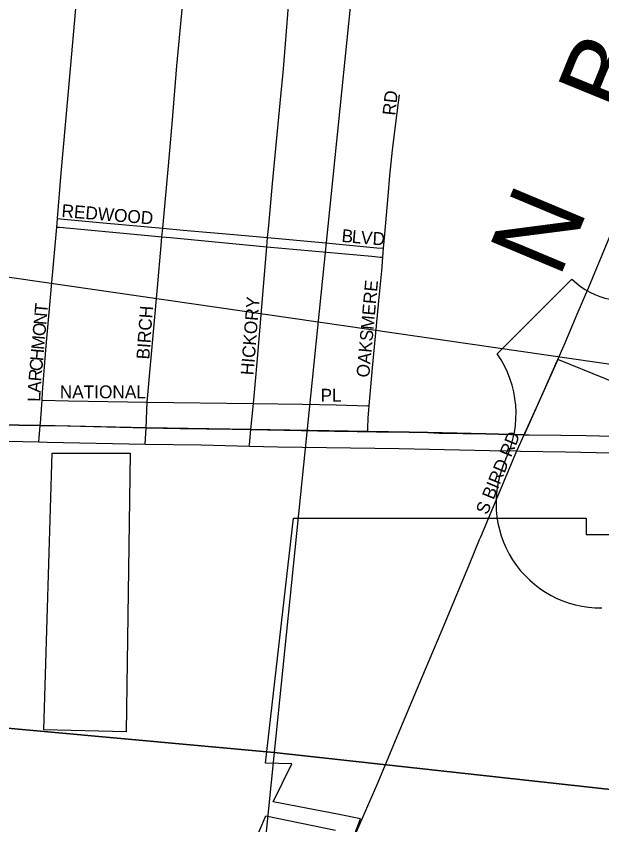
# Model space of a CAD drawing. Extents: x -209 to 4852, y 0 to 905.
# Drawn here: x 185.98 to 194.59, y 266.56 to 278.45 of the extents above; entities that cross this region are included whole.
import ezdxf

# ---------------------------------------------------------------- set-up
doc = ezdxf.new("R2010")
doc.units = 0
for name, color, linetype in [('GM_X_Airport_Location_Class_2', 7, 'Continuous'), ('GM_X_Airport_Location_Class_3', 7, 'Continuous'), ('GM_X_Corporation', 7, 'Continuous'), ('GM_X_County_ROW', 7, 'Continuous'), ('GM_X_Interchange_Ramps', 7, 'Continuous'), ('GM_X_Interstate_Location', 7, 'Continuous'), ('GM_X_Minor_River', 7, 'Continuous'), ('GM_X_Township_Road', 7, 'Continuous'), ('GM_X_Township_Text', 7, 'Continuous'), ('GM_X_US_Location', 7, 'Continuous'), ('SH_Text', 7, 'Continuous')]:
    doc.layers.add(name, color=color, linetype=linetype)

msp = doc.modelspace()

# ---------------------------------------------------------------- linework, layer by layer
at = {"layer": 'GM_X_Airport_Location_Class_2'}
msp.add_lwpolyline([(192.919, 271.064), (193.195, 271.724), (193.339, 272.058)], dxfattribs=at)
at = {"layer": 'GM_X_Corporation'}
for points in [[(185.391, 272.449), (186.331, 272.434), (186.734, 272.427), (187.887, 272.398), (188.395, 272.39), (189.152, 272.38), (189.428, 272.374), (190.657, 272.349), (190.989, 272.344), (191.146, 272.342), (191.275, 272.34), (191.445, 272.338), (191.752, 272.334), (192.029, 272.33), (192.201, 272.322), (192.88, 272.31), (193.444, 272.297), (193.52, 272.296), (193.983, 272.291), (194.355, 272.286), (195.342, 272.263)], [(182.897, 272.238), (182.972, 272.238), (183.815, 272.236), (184.679, 272.224), (185.366, 272.213), (186.311, 272.19), (186.434, 272.187), (187.875, 272.159), (188.695, 272.147), (189.403, 272.131), (189.824, 272.121), (191.605, 272.092), (192.942, 272.066), (193.339, 272.058)], [(193.339, 272.058), (193.389, 272.057), (194.054, 272.046), (194.73, 272.031), (195.342, 272.019)]]:
    msp.add_lwpolyline(points, dxfattribs=at)
at = {"layer": 'GM_X_County_ROW'}
for points in [[(193.625, 272.699), (193.728, 272.927), (193.929, 273.385), (193.938, 273.405), (194.031, 273.613), (194.226, 274.07), (194.394, 274.468), (194.653, 275.094), (194.87, 275.607), (195.228, 276.463), (195.342, 276.74)], [(193.444, 272.297), (193.454, 272.32), (193.625, 272.699)], [(193.339, 272.058), (193.394, 272.187), (193.444, 272.297)], [(190.947, 266.383), (191.079, 266.687), (191.284, 267.154), (191.592, 267.894), (191.899, 268.632), (192.262, 269.487), (192.64, 270.396), (192.79, 270.756), (192.807, 270.797), (192.919, 271.064)]]:
    msp.add_lwpolyline(points, dxfattribs=at)
at = {"layer": 'GM_X_Interchange_Ramps'}
msp.add_line((194.147, 274.584), (193.048, 273.485), dxfattribs=at)
for centre, radius, start, end in [((194.916, 275.368), 1.099, 225.573, 292.8348), ((191.788, 272.603), 1.538, 334.5471, 35.0009), ((194.569, 271.288), 1.538, 154.8319, 270.6383)]:
    msp.add_arc(centre, radius, start, end, dxfattribs=at)
at = {"layer": 'GM_X_Minor_River'}
for points in [[(171.86, 289.687), (191.805, 287.574), (189.771, 267.627), (170.498, 269.384)], [(195.342, 267.012), (195.342, 287.212), (191.805, 287.574), (189.771, 267.627)], [(170.498, 269.384), (189.771, 267.627), (187.727, 247.423), (168.839, 249.556)], [(195.342, 246.562), (195.342, 267.012), (189.771, 267.627), (187.727, 247.423)]]:
    msp.add_lwpolyline(points, close=True, dxfattribs=at)
at = {"layer": 'GM_X_Township_Text'}
for points in [[(186.584, 275.473), (186.64, 276.142), (186.765, 277.562), (186.864, 278.677), (186.92, 279.295), (186.96, 279.728), (186.961, 279.741)], [(188.131, 275.333), (188.215, 276.248), (188.276, 276.927), (188.341, 277.721), (188.433, 278.706), (188.455, 278.952), (188.471, 279.134), (188.505, 279.568), (188.507, 279.595)], [(189.673, 275.194), (189.689, 275.371), (189.746, 275.991), (189.774, 276.3), (189.877, 277.374), (189.901, 277.617), (189.918, 277.8), (189.973, 278.476), (190.02, 279.212), (190.02, 279.281), (190.014, 279.319), (190.001, 279.355), (189.974, 279.393), (189.946, 279.419)], [(191.379, 275.037), (191.397, 275.247), (191.444, 275.802), (191.47, 276.107), (191.509, 276.48), (191.563, 276.915), (191.614, 277.291)], [(186.574, 275.35), (186.578, 275.401), (186.584, 275.473)], [(186.584, 275.473), (186.627, 275.469), (187.255, 275.411), (188.131, 275.333)], [(186.357, 272.803), (186.366, 272.922), (186.414, 273.543), (186.499, 274.534), (186.574, 275.35)], [(186.574, 275.35), (186.616, 275.346), (187.813, 275.234), (188.12, 275.206)], [(188.12, 275.206), (188.131, 275.333)], [(188.131, 275.333), (188.434, 275.306), (189.179, 275.24), (189.673, 275.194)], [(187.905, 272.775), (188.055, 274.459), (188.108, 275.076), (188.12, 275.206)], [(188.12, 275.206), (188.248, 275.194), (189.661, 275.06)], [(189.661, 275.06), (189.673, 275.194)], [(189.673, 275.194), (190.476, 275.12), (191.281, 275.046), (191.379, 275.037)], [(189.464, 272.756), (189.47, 272.811), (189.522, 273.358), (189.661, 275.06)], [(189.661, 275.06), (191.206, 274.921), (191.333, 274.908), (191.368, 274.905)], [(191.368, 274.905), (191.379, 275.037)], [(191.165, 272.721), (191.215, 273.279), (191.273, 273.897), (191.308, 274.266), (191.351, 274.707), (191.368, 274.905)], [(186.331, 272.434), (186.333, 272.468), (186.357, 272.803)], [(186.357, 272.803), (186.744, 272.796), (187.905, 272.775)], [(187.887, 272.398), (187.905, 272.775)], [(187.905, 272.775), (189.464, 272.756)], [(189.428, 272.374), (189.464, 272.756)], [(189.464, 272.756), (190.187, 272.747), (190.68, 272.738), (191.141, 272.722), (191.165, 272.721)], [(191.146, 272.342), (191.147, 272.392), (191.152, 272.538), (191.159, 272.661), (191.165, 272.721)], [(186.311, 272.19), (186.315, 272.252), (186.331, 272.434)], [(187.875, 272.159), (187.887, 272.398)], [(189.403, 272.131), (189.405, 272.15), (189.428, 272.374)]]:
    msp.add_lwpolyline(points, dxfattribs=at)
at = {"layer": 'GM_X_US_Location'}
for points in [[(195.342, 272.835), (193.938, 273.405), (193.444, 272.297), (192.88, 272.31), (192.029, 272.33), (191.752, 272.334), (191.146, 272.342), (189.428, 272.374), (187.887, 272.398), (186.331, 272.434), (185.391, 272.449), (185.389, 272.745), (183.888, 272.478), (182.868, 272.5), (177.7, 272.574)], [(190.931, 266.367), (191.04, 266.65), (190.725, 266.713), (189.754, 266.9), (190.029, 267.457), (189.642, 267.467), (190.054, 271.071), (194.357, 271.071), (194.357, 270.829), (195.342, 270.829)], [(188.631, 264.321), (189.649, 266.696), (190.672, 266.485)]]:
    msp.add_lwpolyline(points, dxfattribs=at)
msp.add_lwpolyline([(186.504, 272.024), (187.655, 272.024), (187.595, 267.93), (186.382, 267.961)], close=True, dxfattribs=at)
at = {"layer": 'SH_Text'}
msp.add_lwpolyline([(110.173, 285.569), (202.362, 278.085), (232.041, 278.085), (232.041, 272.446), (202.369, 272.22)], close=True, dxfattribs=at)

# ---------------------------------------------------------------- texts
at = {"layer": 'GM_X_Airport_Location_Class_3'}
msp.add_text('S BIRD RD', height=0.1894, rotation=67.576, dxfattribs=at).set_placement((192.902, 271.11))
at = {"layer": 'GM_X_Interstate_Location'}
for s, height, rotation, p in [('RD', 0.1894, 83.982, (191.55, 276.983)), ('REDWOOD', 0.1894, 355.2389, (186.638, 275.498)), ('B', 0.189, 354.821, (190.755, 275.132)), ('L', 0.189, 354.8031, (190.905, 275.118)), ('V', 0.189, 354.8138, (191.037, 275.106)), ('D', 0.189, 357.1239, (191.212, 275.09)), ('OAKSMERE', 0.1894, 84.7363, (191.166, 273.132)), ('T', 0.189, 84.9391, (186.434, 274.071)), ('HICKORY', 0.1894, 85.4615, (189.466, 273.166)), ('BIRCH', 0.1894, 85.9114, (187.933, 273.399)), ('N', 0.189, 84.9472, (186.419, 273.905)), ('O', 0.189, 84.9472, (186.404, 273.739)), ('M', 0.189, 84.9363, (186.387, 273.54)), ('H', 0.189, 84.9223, (186.372, 273.374)), ('C', 0.189, 84.9419, (186.359, 273.224)), ('R', 0.189, 84.9661, (186.345, 273.075)), ('A', 0.189, 86.2819, (186.335, 272.91)), ('NATIONAL', 0.1894, 0, (186.618, 272.832)), ('PL', 0.1894, 0, (190.452, 272.782)), ('L', 0.189, 89.0711, (186.333, 272.779))]:
    msp.add_text(s, height=height, rotation=rotation, dxfattribs=at).set_placement(p)
at = {"layer": 'GM_X_Township_Road'}
for s, rotation, p in [('B', 67.8239, (194.958, 276.947)), ('N', 67.301, (193.959, 274.582))]:
    msp.add_text(s, height=1.136, rotation=rotation, dxfattribs=at).set_placement(p)

doc.saveas('drawing.dxf')
